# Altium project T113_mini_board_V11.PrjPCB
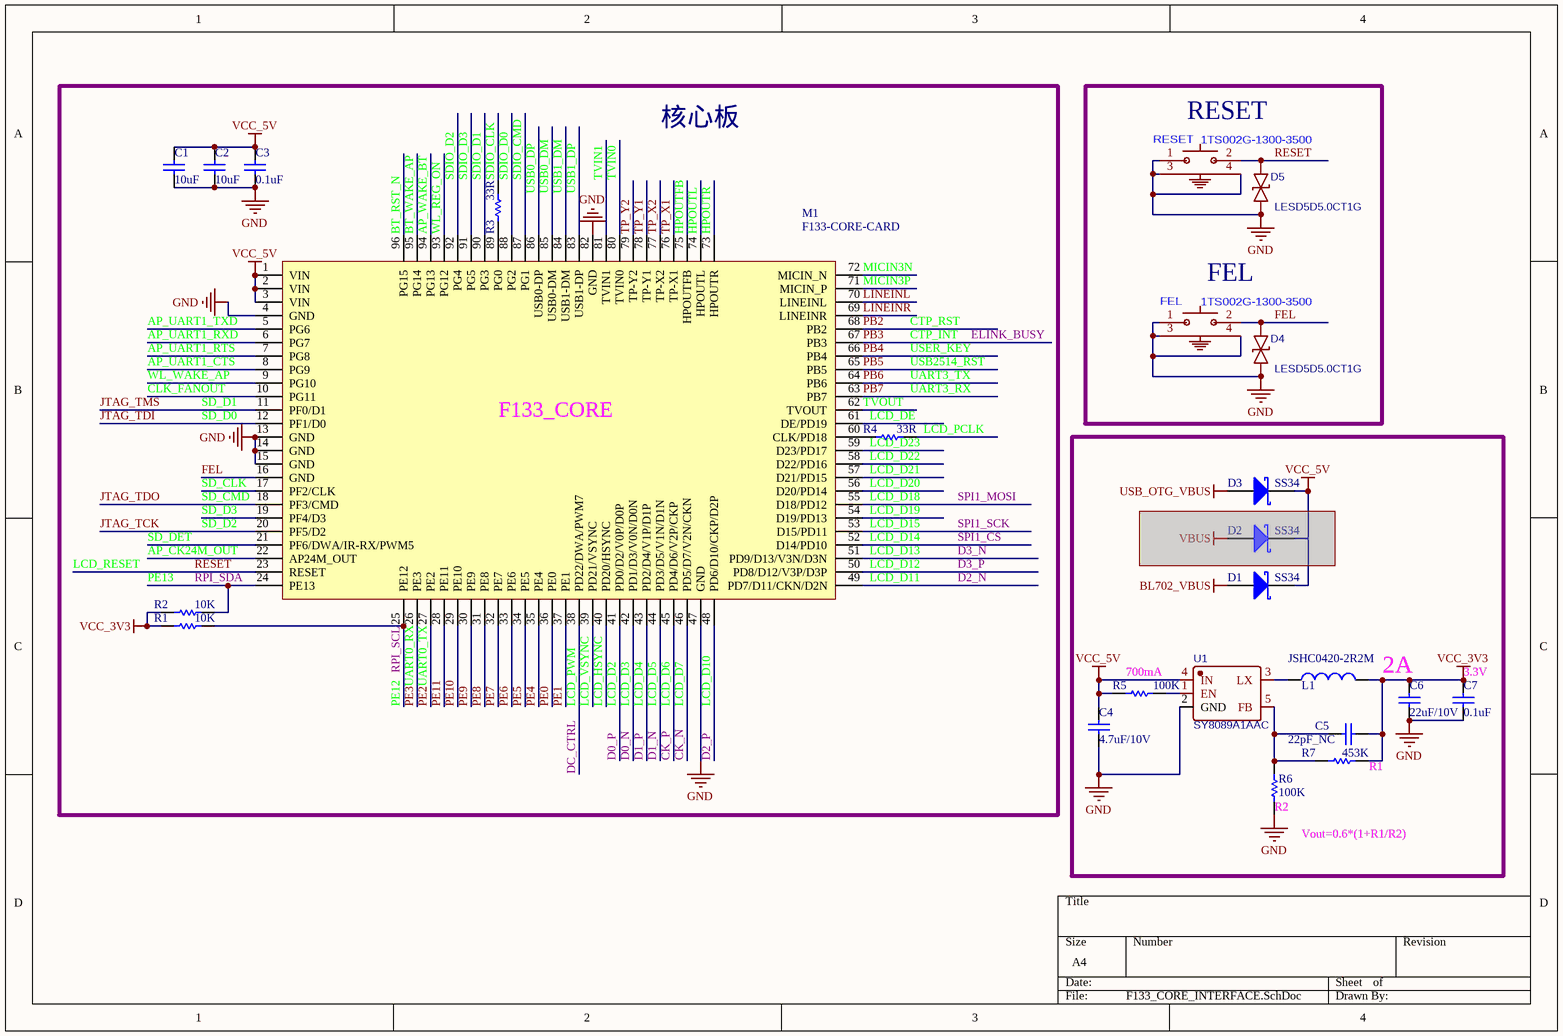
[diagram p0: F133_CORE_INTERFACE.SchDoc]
4 sheets, 114 parts. Net scope: global (net labels, ports and power ports of the same name join across sheets).
Board file: T113_mini_board_V11.PcbDoc
Sheets:
  F133_CORE_INTERFACE.SchDoc
  USB_OTG&DEBUG&TF.SchDoc
  INTERFACE.SchDoc
  BL702.SchDoc

## Sheet F133_CORE_INTERFACE.SchDoc
size A4

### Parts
C1  10uF  [0402]
C2  10uF  [0402]
C3  0.1uF  [0402]
C4  4.7uF/10V  [0402]
C5  22pF_NC  [0402]
C6  22uF/10V  [0603]
C7  0.1uF  [0402]
D1  SS34  [SMA]
D2  SS34  [SMA]  (masked out: inside a compile mask, not in the netlist)
D3  SS34  [SMA]
D4  LESD5D5.0CT1G  [SOD-523_L1.2-W0.8-LS1.6-BI]
D5  LESD5D5.0CT1G  [SOD-523_L1.2-W0.8-LS1.6-BI]
FEL  1TS002G-1300-3500  [SW-SMD_1TS002G-XXXX-3500-CT]
L1  JSHC0420-2R2M  [IND-SMD_L4.9-W4.5]
M1  F133-CORE-CARD  [F133_CORE_V10]
R1  10K  [0402]
R2  10K  [0402]
R3  33R  [0402]
R4  33R  [0402]
R5  100K  [0402]
R6  100K  [0402]
R7  453K  [0402]
RESET  1TS002G-1300-3500  [SW-SMD_1TS002G-XXXX-3500-CT]
U1  SY8089A1AAC  [SOT-23-5_L3.0-W1.7-P0.95-LS2.8-BL]

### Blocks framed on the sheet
核心板: C1-C3 M1 R1-R4
2A: C4-C7 D1-D3 L1 R5-R7 U1

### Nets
BL702_VBUS: D1.1(A)
GND: C1.1 C2.1 C3.1 C4.1 C6.1 C7.1 D4.1 D5.1 FEL.1 FEL.3 FEL.4 M1.4(GND) M1.13(GND) M1.14(GND) M1.15(GND) M1.47(GND) M1.82(GND) R6.2 RESET.1 RESET.3 RESET.4 U1.2(GND)
USB_OTG_VBUS: D3.1(A)
VCC_3V3: C5.2 C6.2 C7.2 L1.2 R1.2 R2.2 R7.1  [project net SYS_3V3]
VCC_5V: C1.2 C2.2 C3.2 C4.2 D1.2(K) D3.2(K) M1.1(VIN) M1.2(VIN) M1.3(VIN) R5.2 U1.4(IN)
AP_CK24M_OUT: M1.22(AP24M_OUT)
AP_UART1_CTS: M1.8(PG9)
AP_UART1_RTS: M1.7(PG8)
AP_UART1_RXD: M1.6(PG7)
AP_UART1_TXD: M1.5(PG6)
AP_WAKE_BT: M1.94(PG13)
BT_RST_N: M1.96(PG15)
BT_WAKE_AP: M1.95(PG14)
CK_N: M1.46(PD5/D7/V2N/CKN)  [also labelled LCD_D7]
CK_P: M1.45(PD4/D6/V2P/CKP)  [also labelled LCD_D6]
CLK_FANOUT: M1.10(PG11)
CTP_INT: M1.67(PB3)  [also labelled ELINK_BUSY, PB3]
CTP_RST: M1.68(PB2)  [also labelled PB2]
D0_N: M1.42(PD1/D3/V0N/D0N)  [also labelled LCD_D3]
D0_P: M1.41(PD0/D2/V0P/D0P)  [also labelled LCD_D2]
D1_N: M1.44(PD3/D5/V1N/D1N)  [also labelled LCD_D5]
D1_P: M1.43(PD2/D4/V1P/D1P)  [also labelled LCD_D4]
D2_N: M1.49(PD7/D11/CKN/D2N)  [also labelled LCD_D11]
D2_P: M1.48(PD6/D10/CKP/D2P)  [also labelled LCD_D10]
D3_N: M1.51(PD9/D13/V3N/D3N)  [also labelled LCD_D13]
D3_P: M1.50(PD8/D12/V3P/D3P)  [also labelled LCD_D12]
DC_CTRL: M1.38(PD22/DWA/PWM7)  [also labelled LCD_PWM]
FEL: D4.2 FEL.2 M1.16(GND)
HPOUTFB: M1.75(HPOUTFB)
HPOUTL: M1.74(HPOUTL)
HPOUTR: M1.73(HPOUTR)
JTAG_TCK: M1.20(PF5/D2)  [also labelled SD_D2]
JTAG_TDI: M1.12(PF1/D0)  [also labelled SD_D0]
JTAG_TDO: M1.18(PF3/CMD)  [also labelled SD_CMD]
JTAG_TMS: M1.11(PF0/D1)  [also labelled SD_D1]
LCD_D14: M1.52(D14/PD10)  [also labelled SPI1_CS]
LCD_D15: M1.53(D15/PD11)  [also labelled SPI1_SCK]
LCD_D18: M1.55(D18/PD12)  [also labelled SPI1_MOSI]
LCD_D19: M1.54(D19/PD13)
LCD_D20: M1.56(D20/PD14)
LCD_D21: M1.57(D21/PD15)
LCD_D22: M1.58(D22/PD16)
LCD_D23: M1.59(D23/PD17)
LCD_DE: M1.61(DE/PD19)
LCD_HSYNC: M1.40(PD20/HSYNC)
LCD_PCLK: R4.2
LCD_RESET: D5.2 M1.23(RESET) RESET.2  [also labelled RESET]
LCD_VSYNC: M1.39(PD21/VSYNC)
LINEINL: M1.70(LINEINL)
LINEINR: M1.69(LINEINR)
MICIN3N: M1.72(MICIN_N)
MICIN3P: M1.71(MICIN_P)
PB4: M1.66(PB4)  [also labelled USER_KEY]
PB5: M1.65(PB5)  [also labelled USB2514_RST]
PB6: M1.64(PB6)  [also labelled UART3_TX]
PB7: M1.63(PB7)  [also labelled UART3_RX]
PE0: M1.36(PE0)
PE1: M1.37(PE1)
PE2: M1.27(PE2)  [also labelled UART0_TX]  [project net BL702_U1RX]
PE3: M1.26(PE3)  [also labelled UART0_RX]  [project net BL702_U1TX]
PE4: M1.35(PE4)
PE5: M1.34(PE5)
PE6: M1.33(PE6)
PE7: M1.32(PE7)
PE8: M1.31(PE8)
PE9: M1.30(PE9)
PE10: M1.29(PE10)
PE11: M1.28(PE11)
PE12: M1.25(PE12) R1.1  [also labelled RPI_SCL]
PE13: M1.24(PE13) R2.1  [also labelled RPI_SDA]
SD_CLK: M1.17(PF2/CLK)
SD_D3: M1.19(PF4/D3)
SD_DET: M1.21(PF6/DWA/IR-RX/PWM5)
SDIO_CLK: R3.1
SDIO_CMD: M1.87(PG1)
SDIO_D0: M1.88(PG2)
SDIO_D1: M1.90(PG3)
SDIO_D2: M1.92(PG4)
SDIO_D3: M1.91(PG5)
TP_X1: M1.76(TP-X1)
TP_X2: M1.77(TP-X2)
TP_Y1: M1.78(TP-Y1)
TP_Y2: M1.79(TP-Y2)
TVIN0: M1.80(TVIN0)
TVIN1: M1.81(TVIN1)
TVOUT: M1.62(TVOUT)
USB0_DM: M1.85(USB0-DM)
USB0_DP: M1.86(USB0-DP)
USB1_DM: M1.84(USB1-DM)
USB1_DP: M1.83(USB1-DP)
WL_REG_ON: M1.93(PG12)
WL_WAKE_AP: M1.9(PG10)
NetC5_1: C5.1 R6.1 R7.2 U1.5(FB)
NetL1_1: L1.1 U1.3(LX)
NetM1_60: M1.60(CLK/PD18) R4.1
NetM1_89: M1.89(PG0) R3.2
NetR5_1: R5.1 U1.1(EN)

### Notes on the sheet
- RESET
- FEL
- (near R5) 700mA
- (near C7) 3.3V
- (near R7) R1
- (near R6) R2
- (near R6) Vout=0.6*(1+R1/R2)

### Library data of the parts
C1-C7 = Cap: Capacitor; PartNumber: CAP100NF
D1-D3 = D Schottky: Schottky Diode
D4 D5 = LESD5D5.0CT1G: BOM_Manufacturer: Leshan Radio; Contributor: LCSC
L1 = Inductor: PartNumber: IND10UH; Code_IEC: 1005
M1 = F133_CORE
R1-R7 = Res1: Resistor; PartNumber: RES2.2K
U1 = SY8089A1AAC: BOM_Manufacturer: Silergy Corp; Contributor: LCSC

## Sheet USB_OTG&DEBUG&TF.SchDoc
size A4
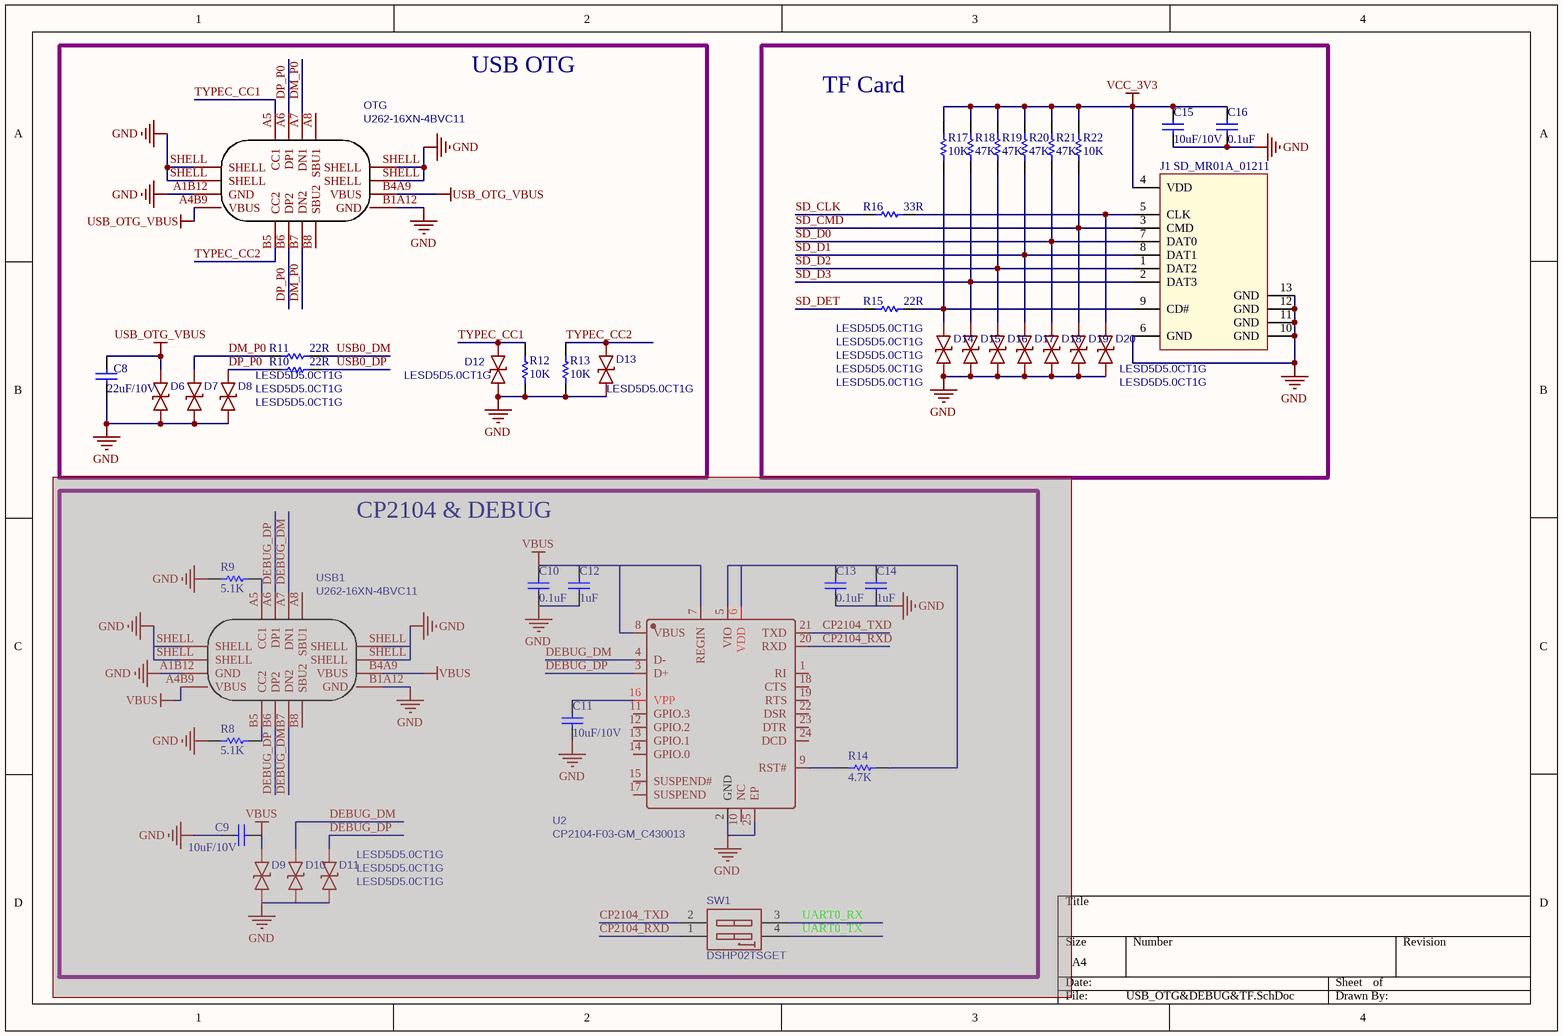
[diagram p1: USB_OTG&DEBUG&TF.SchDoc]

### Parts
C8  22uF/10V  [0603]
C9  10uF/10V  [0402]  (masked out: inside a compile mask, not in the netlist)
C10  0.1uF  [0402]  (masked out: inside a compile mask, not in the netlist)
C11  10uF/10V  [0402]  (masked out: inside a compile mask, not in the netlist)
C12  1uF  [0402]  (masked out: inside a compile mask, not in the netlist)
C13  0.1uF  [0402]  (masked out: inside a compile mask, not in the netlist)
C14  1uF  [0402]  (masked out: inside a compile mask, not in the netlist)
C15  10uF/10V  [0402]
C16  0.1uF  [0402]
D6  LESD5D5.0CT1G  [SOD-523_L1.2-W0.8-LS1.6-BI]
D7  LESD5D5.0CT1G  [SOD-523_L1.2-W0.8-LS1.6-BI]
D8  LESD5D5.0CT1G  [SOD-523_L1.2-W0.8-LS1.6-BI]
D9  LESD5D5.0CT1G  [SOD-523_L1.2-W0.8-LS1.6-BI]  (masked out: inside a compile mask, not in the netlist)
D10  LESD5D5.0CT1G  [SOD-523_L1.2-W0.8-LS1.6-BI]  (masked out: inside a compile mask, not in the netlist)
D11  LESD5D5.0CT1G  [SOD-523_L1.2-W0.8-LS1.6-BI]  (masked out: inside a compile mask, not in the netlist)
D12  LESD5D5.0CT1G  [SOD-523_L1.2-W0.8-LS1.6-BI]
D13  LESD5D5.0CT1G  [SOD-523_L1.2-W0.8-LS1.6-BI]
D14  LESD5D5.0CT1G  [SOD-523_L1.2-W0.8-LS1.6-BI]
D15  LESD5D5.0CT1G  [SOD-523_L1.2-W0.8-LS1.6-BI]
D16  LESD5D5.0CT1G  [SOD-523_L1.2-W0.8-LS1.6-BI]
D17  LESD5D5.0CT1G  [SOD-523_L1.2-W0.8-LS1.6-BI]
D18  LESD5D5.0CT1G  [SOD-523_L1.2-W0.8-LS1.6-BI]
D19  LESD5D5.0CT1G  [SOD-523_L1.2-W0.8-LS1.6-BI]
D20  LESD5D5.0CT1G  [SOD-523_L1.2-W0.8-LS1.6-BI]
J1  SD_MR01A_01211  [SD-MR01A-01211]
OTG  U262-16XN-4BVC11  [TYPEC-12PIN - duplicate]
R8  5.1K  [0402]  (masked out: inside a compile mask, not in the netlist)
R9  5.1K  [0402]  (masked out: inside a compile mask, not in the netlist)
R10  22R  [0402]
R11  22R  [0402]
R12  10K  [0402]
R13  10K  [0402]
R14  4.7K  [0402]  (masked out: inside a compile mask, not in the netlist)
R15  22R  [0402]
R16  33R  [0402]
R17  10K  [0402]
R18  47K  [0402]
R19  47K  [0402]
R20  47K  [0402]
R21  47K  [0402]
R22  10K  [0402]
SW1  DSHP02TSGET  [SW-SMD_4P_DSHP02TSGET]  (masked out: inside a compile mask, not in the netlist)
U2  CP2104-F03-GM_C430013  [QFN-24_L4.0-W4.0-P0.50-TL-EP2.7]  (masked out: inside a compile mask, not in the netlist)
USB1  U262-16XN-4BVC11  [TYPEC-12PIN - duplicate]  (masked out: inside a compile mask, not in the netlist)

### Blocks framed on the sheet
USB OTG: C8 D6-D8 D12 D13 OTG R10-R13
TF Card: C15 C16 D14-D20 J1 R15-R22
CP2104 & DEBUG: C9-C14 D9-D11 R8 R9 R14 SW1 U2 USB1

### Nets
GND: C8.1 C15.2 C16.2 D6.1 D7.1 D8.1 D12.1 D13.1 D14.1 D15.1 D16.1 D17.1 D18.1 D19.1 D20.1 J1.6(GND) J1.10(GND) J1.11(GND) J1.12(GND) J1.13(GND) OTG.A1B12(GND) OTG.B1A12(GND) OTG.SHELL R12.1 R13.1
USB_OTG_VBUS: C8.2 D6.2 OTG.A4B9(VBUS) OTG.B4A9(VBUS)
VCC_3V3: C15.1 C16.1 J1.4(VDD) R17.1 R18.1 R19.1 R20.1 R21.1 R22.1  [project net SYS_3V3]
DM_P0: D7.2 OTG.A7(DN1) OTG.B7(DN2) R11.1
DP_P0: D8.2 OTG.A6(DP1) OTG.B6(DP2) R10.1
SD_CLK: R16.2
SD_CMD: D19.2 J1.3(CMD) R22.2  [project net JTAG_TDO]
SD_D0: D18.2 J1.7(DAT0) R21.2  [project net JTAG_TDI]
SD_D1: D17.2 J1.8(DAT1) R20.2  [project net JTAG_TMS]
SD_D2: D16.2 J1.1(DAT2) R19.2  [project net JTAG_TCK]
SD_D3: D15.2 J1.2(DAT3) R18.2
SD_DET: R15.2
TYPEC_CC1: D12.2 OTG.A5(CC1) R12.2
TYPEC_CC2: D13.2 OTG.B5(CC2) R13.2
USB0_DM: R11.2
USB0_DP: R10.2
NetD14_2: D14.2 J1.9(CD#) R15.1 R17.2
NetD20_2: D20.2 J1.5(CLK) R16.1

Not connected (* = marked no-connect by the designer): OTG A8(SBU1) B8(SBU2)

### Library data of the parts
C8-C16 = Cap: Capacitor; PartNumber: CAP100NF
D6-D13 = LESD5D5.0CT1G: as D4 on sheet F133_CORE_INTERFACE
D14-D20 = LESD5D5.0CT1G: BOM_Manufacturer: Leshan Radio; Contributor: LCSC; BOM_Paste Type: expand
OTG USB1 = U262-16XN-4BVC11: BOM_Manufacturer: XKB Enterprise; Contributor: LCSC
R8 R9 R14-R22 = Res1: Resistor; PartNumber: RES2.2K
R10-R13 = Res1: Resistor; PartNumber: RES22R
SW1 = DSHP02TSGET: BOM_Manufacturer: KE
U2 = CP2104-F03-GM_C430013: BOM_Manufacturer: SILICON LABS; Contributor: LCSC

## Sheet INTERFACE.SchDoc
size A4
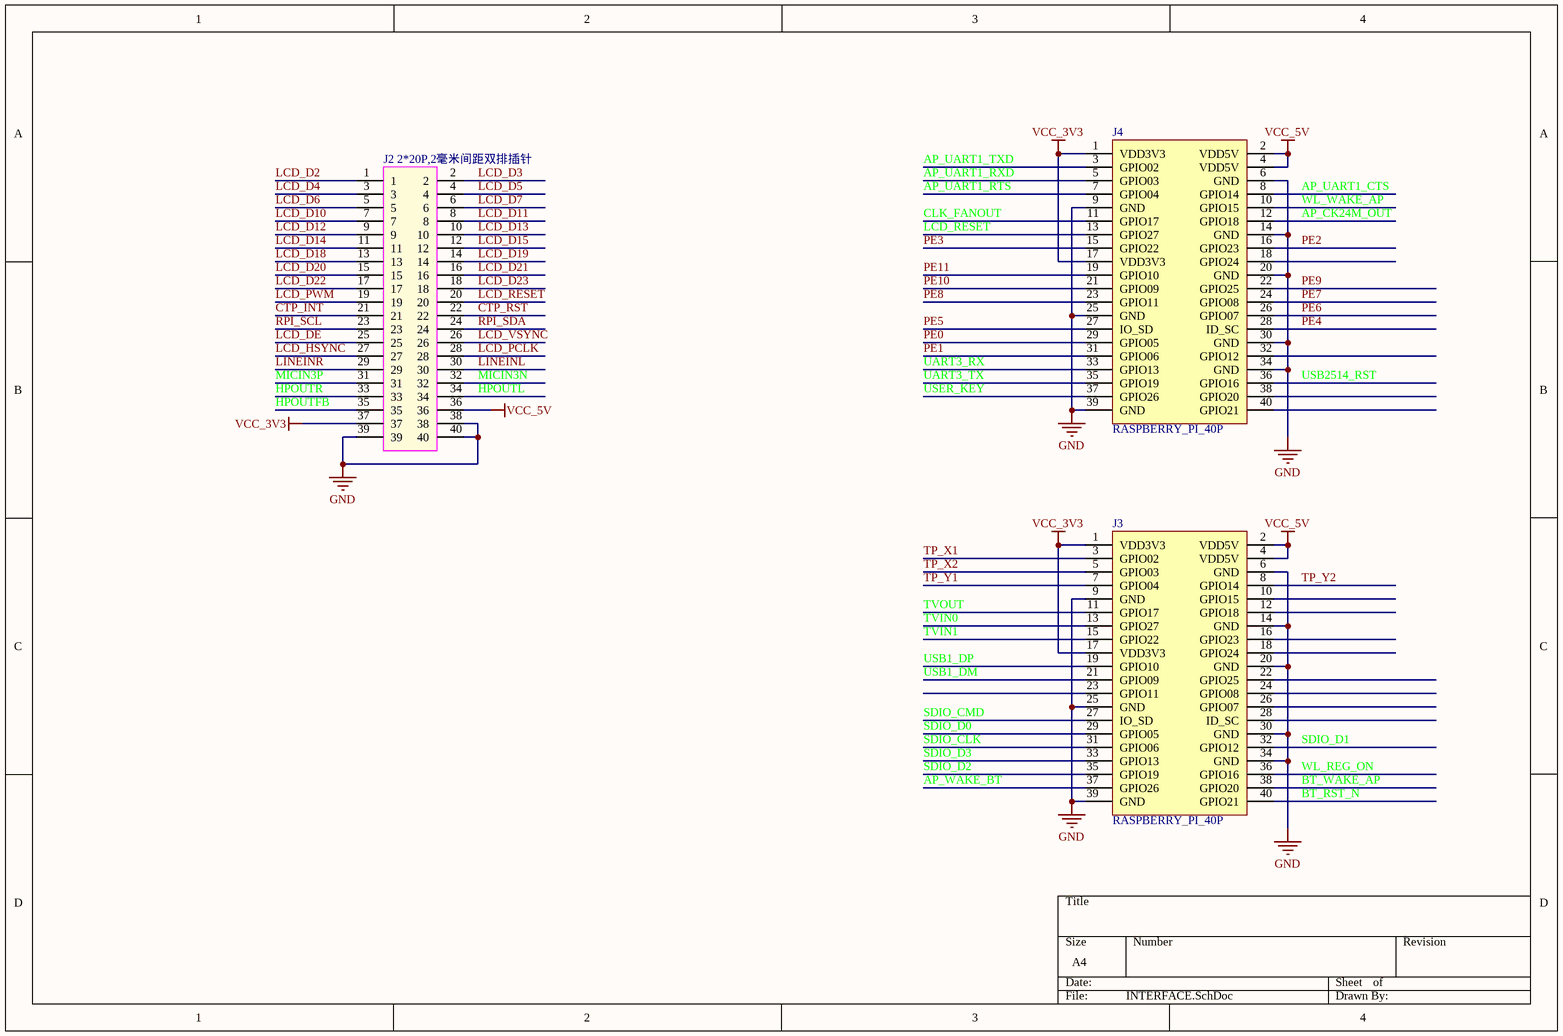
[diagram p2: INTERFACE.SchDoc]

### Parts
J2  2*20P,2毫米间距双排插针  [HDR-TH_40P-P2.00-V-M-R2-C20-S2.00]
J3  RASPBERRY_PI_40P  [IDE2X20]
J4  RASPBERRY_PI_40P  [IDE2X20]

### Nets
GND: J2.38 J2.39 J2.40 J3.6(GND) J3.9(GND) J3.14(GND) J3.20(GND) J3.25(GND) J3.30(GND) J3.34(GND) J3.39(GND) J4.6(GND) J4.9(GND) J4.14(GND) J4.20(GND) J4.25(GND) J4.30(GND) J4.34(GND) J4.39(GND)
VCC_3V3: J2.37 J3.1(VDD3V3) J3.17(VDD3V3) J4.1(VDD3V3) J4.17(VDD3V3)  [project net SYS_3V3]
VCC_5V: J2.36 J3.2(VDD5V) J3.4(VDD5V) J4.2(VDD5V) J4.4(VDD5V)
AP_CK24M_OUT: J4.12(GPIO18)
AP_UART1_CTS: J4.8(GPIO14)
AP_UART1_RTS: J4.7(GPIO04)
AP_UART1_RXD: J4.5(GPIO03)
AP_UART1_TXD: J4.3(GPIO02)
AP_WAKE_BT: J3.37(GPIO26)
BT_RST_N: J3.40(GPIO21)
BT_WAKE_AP: J3.38(GPIO20)
CLK_FANOUT: J4.11(GPIO17)
CTP_INT: J2.21
CTP_RST: J2.22
HPOUTFB: J2.35
HPOUTL: J2.34
HPOUTR: J2.33
LCD_D2: J2.1  [project net D0_P]
LCD_D3: J2.2  [project net D0_N]
LCD_D4: J2.3  [project net D1_P]
LCD_D5: J2.4  [project net D1_N]
LCD_D6: J2.5  [project net CK_P]
LCD_D7: J2.6  [project net CK_N]
LCD_D10: J2.7  [project net D2_P]
LCD_D11: J2.8  [project net D2_N]
LCD_D12: J2.9  [project net D3_P]
LCD_D13: J2.10  [project net D3_N]
LCD_D14: J2.11
LCD_D15: J2.12
LCD_D18: J2.13
LCD_D19: J2.14
LCD_D20: J2.15
LCD_D21: J2.16
LCD_D22: J2.17
LCD_D23: J2.18
LCD_DE: J2.25
LCD_HSYNC: J2.27
LCD_PCLK: J2.28
LCD_PWM: J2.19  [project net DC_CTRL]
LCD_RESET: J2.20 J4.13(GPIO27)
LCD_VSYNC: J2.26
LINEINL: J2.30
LINEINR: J2.29
MICIN3N: J2.32
MICIN3P: J2.31
PE0: J4.29(GPIO05)
PE1: J4.31(GPIO06)
PE2: J4.16(GPIO23)  [project net BL702_U1RX]
PE3: J4.15(GPIO22)  [project net BL702_U1TX]
PE4: J4.28(ID_SC)
PE5: J4.27(IO_SD)
PE6: J4.26(GPIO07)
PE7: J4.24(GPIO08)
PE8: J4.23(GPIO11)
PE9: J4.22(GPIO25)
PE10: J4.21(GPIO09)
PE11: J4.19(GPIO10)
RPI_SCL: J2.23  [project net PE12]
RPI_SDA: J2.24  [project net PE13]
SDIO_CLK: J3.31(GPIO06)
SDIO_CMD: J3.27(IO_SD)
SDIO_D0: J3.29(GPIO05)
SDIO_D1: J3.32(GPIO12)
SDIO_D2: J3.35(GPIO19)
SDIO_D3: J3.33(GPIO13)
TP_X1: J3.3(GPIO02)
TP_X2: J3.5(GPIO03)
TP_Y1: J3.7(GPIO04)
TP_Y2: J3.8(GPIO14)
TVIN0: J3.13(GPIO27)
TVIN1: J3.15(GPIO22)
TVOUT: J3.11(GPIO17)
UART3_RX: J4.33(GPIO13)  [project net PB7]
UART3_TX: J4.35(GPIO19)  [project net PB6]
USB1_DM: J3.21(GPIO09)
USB1_DP: J3.19(GPIO10)
USB2514_RST: J4.36(GPIO16)  [project net PB5]
USER_KEY: J4.37(GPIO26)  [project net PB4]
WL_REG_ON: J3.36(GPIO16)
WL_WAKE_AP: J4.10(GPIO15)

Not connected (* = marked no-connect by the designer): J3 10(GPIO15) 12(GPIO18) 16(GPIO23) 18(GPIO24) 22(GPIO25) 23(GPIO11) 24(GPIO08) 26(GPIO07) 28(ID_SC); J4 18(GPIO24) 32(GPIO12) 38(GPIO20) 40(GPIO21)

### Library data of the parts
J2 = IDC40
J3 J4 = RASPBERRY_PI: Value: 40P树莓派接口插针

## Sheet BL702.SchDoc
size A4
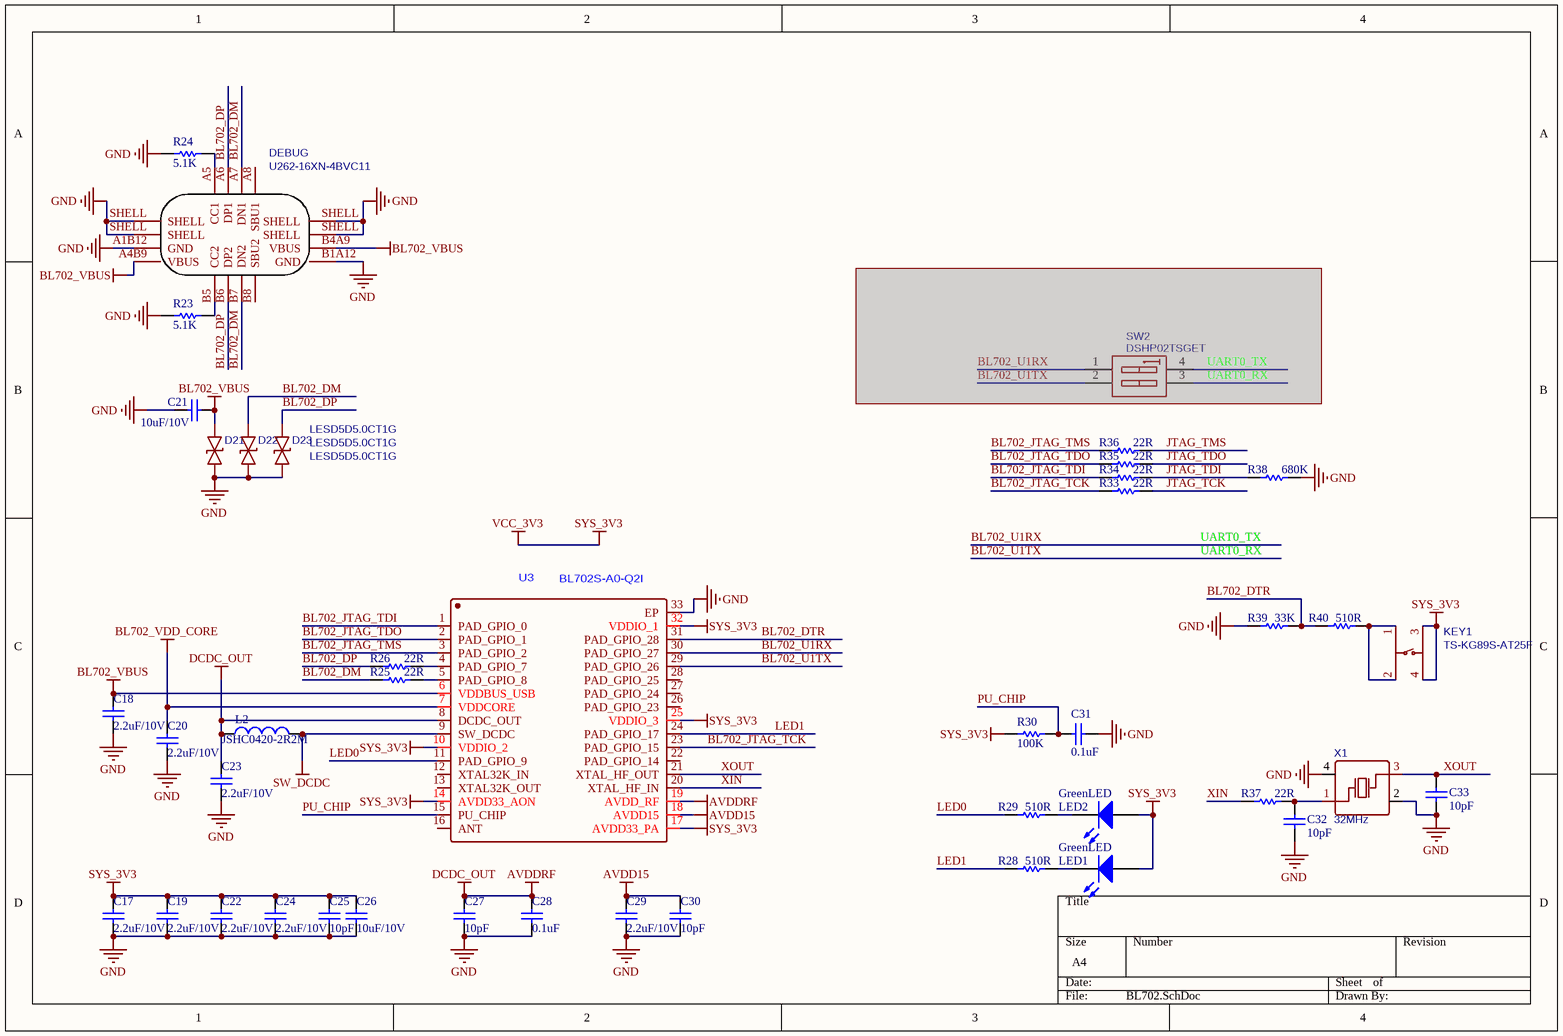
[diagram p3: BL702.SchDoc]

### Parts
C17  2.2uF/10V  [0402]
C18  2.2uF/10V  [0402]
C19  2.2uF/10V  [0402]
C20  2.2uF/10V  [0402]
C21  10uF/10V  [0402]
C22  2.2uF/10V  [0402]
C23  2.2uF/10V  [0402]
C24  2.2uF/10V  [0402]
C25  10pF  [0402]
C26  10uF/10V  [0402]
C27  10pF  [0402]
C28  0.1uF  [0402]
C29  2.2uF/10V  [0402]
C30  10pF  [0402]
C31  0.1uF  [0402]
C32  10pF  [0402]
C33  10pF  [0402]
D21  LESD5D5.0CT1G  [SOD-523_L1.2-W0.8-LS1.6-BI]
D22  LESD5D5.0CT1G  [SOD-523_L1.2-W0.8-LS1.6-BI]
D23  LESD5D5.0CT1G  [SOD-523_L1.2-W0.8-LS1.6-BI]
DEBUG  U262-16XN-4BVC11  [TYPEC-12PIN - duplicate]
KEY1  TS-KG89S-AT25F  [SW-SMD_4P-L4.2-W3.3-P2.15-LS5.1]
L2  JSHC0420-2R2M  [IND-SMD_L4.9-W4.5]
LED1  GreenLED  [LED0402]
LED2  GreenLED  [LED0402]
R23  5.1K  [0402]
R24  5.1K  [0402]
R25  22R  [0402]
R26  22R  [0402]
R28  510R  [0402]
R29  510R  [0402]
R30  100K  [0402]
R33  22R  [0402]
R34  22R  [0402]
R35  22R  [0402]
R36  22R  [0402]
R37  22R  [0402]
R38  680K  [0402]
R39  33K  [0402]
R40  510R  [0402]
SW2  DSHP02TSGET  [SW-SMD_4P_DSHP02TSGET]  (masked out: inside a compile mask, not in the netlist)
U3  BL702S-A0-Q2I  [QFN-32_L4.0-W4.0-P0.40-TL-EP2.9]
X1  32MHz  [OSC-SMD_4P-L3.2-W2.5-BL]

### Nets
AVDD15: C29.2 C30.2 U3.18(AVDD15)
AVDDRF: C23.2 C27.2 C28.2 L2.1 U3.8(DCDC_OUT) U3.19(AVDD_RF)  [also labelled DCDC_OUT]
BL702_VBUS: C18.2 C21.2 D21.2 DEBUG.A4B9(VBUS) DEBUG.B4A9(VBUS) U3.6(VDDBUS_USB)
BL702_VDD_CORE: C20.2 U3.7(VDDCORE)
GND: C17.1 C18.1 C19.1 C20.1 C21.1 C22.1 C23.1 C24.1 C25.1 C26.1 C27.1 C28.1 C29.1 C30.1 C31.1 C32.1 C33.1 D21.1 D22.1 D23.1 DEBUG.A1B12(GND) DEBUG.B1A12(GND) DEBUG.SHELL R23.2 R24.2 R38.1 R39.2 U3.33(EP) X1.2(GND) X1.4(GND)
SW_DCDC: L2.2 U3.9(SW_DCDC)
SYS_3V3: C17.2 C19.2 C22.2 C24.2 C25.2 C26.2 KEY1.3 KEY1.4 LED1.1(A) LED2.1(A) R30.1 U3.10(VDDIO_2) U3.14(AVDD33_AON) U3.17(AVDD33_PA) U3.25(VDDIO_3) U3.32(VDDIO_1)  [also labelled VCC_3V3]
BL702_DM: D22.2 DEBUG.A7(DN1) DEBUG.B7(DN2) R25.2
BL702_DP: D23.2 DEBUG.A6(DP1) DEBUG.B6(DP2) R26.2
BL702_DTR: R39.1 R40.1 U3.31(PAD_GPIO_28)
BL702_JTAG_TCK: R33.2 U3.23(PAD_GPIO_15)
BL702_JTAG_TDI: R34.2 U3.1(PAD_GPIO_0)
BL702_JTAG_TDO: R35.2 U3.2(PAD_GPIO_1)
BL702_JTAG_TMS: R36.2 U3.3(PAD_GPIO_2)
BL702_U1RX: U3.30(PAD_GPIO_27)  [also labelled UART0_TX]
BL702_U1TX: U3.29(PAD_GPIO_26)  [also labelled UART0_RX]
JTAG_TCK: R33.1
JTAG_TDI: R34.1 R38.2
JTAG_TDO: R35.1
JTAG_TMS: R36.1
LED0: R29.1 U3.11(PAD_GPIO_9)
LED1: R28.1 U3.24(PAD_GPIO_17)
PU_CHIP: C31.2 R30.2 U3.15(PU_CHIP)
XIN: R37.2 U3.20(XTAL_HF_IN)
XOUT: C33.2 U3.21(XTAL_HF_OUT) X1.3(OSC2)
NetC32_2: C32.2 R37.1 X1.1(OSC1)
NetDEBUG_A5: DEBUG.A5(CC1) R24.1
NetDEBUG_B5: DEBUG.B5(CC2) R23.1
NetKEY1_1: KEY1.1 KEY1.2 R40.2
NetLED1_2: LED1.2(K) R28.2
NetLED2_2: LED2.2(K) R29.2
NetR25_1: R25.1 U3.5(PAD_GPIO_8)
NetR26_1: R26.1 U3.4(PAD_GPIO_7)

Not connected (* = marked no-connect by the designer): DEBUG A8(SBU1) B8(SBU2); U3 12(XTAL32K_IN) 13(XTAL32K_OUT) 16(ANT) 22(PAD_GPIO_14) 26(PAD_GPIO_23) 27(PAD_GPIO_24) 28(PAD_GPIO_25)

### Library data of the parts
C17-C33 = Cap: Capacitor; PartNumber: CAP100NF
D21-D23 = LESD5D5.0CT1G: as D4 on sheet F133_CORE_INTERFACE
DEBUG = U262-16XN-4BVC11: as OTG on sheet USB_OTG&DEBUG&TF
KEY1 = TS-KG89S-AT25F: Contributor: LCSC
L2 = Inductor: PartNumber: IND10UH; Code_IEC: 1005
LED1 LED2 = LED2: Typical RED, GREEN, YELLOW, AMBER GaAs LED
R23 R24 R28-R30 R40 = Res1: Resistor; PartNumber: RES2.2K
R25 R26 R33-R39 = Res1: Resistor; PartNumber: RES22R
SW2 = DSHP02TSGET: BOM_Manufacturer: KE
X1 = 24MHz_1: BOM_Manufacturer: JGHC; BOM_Manufacturer Part: S3224000151050; nameAlias: Frequency; Contributor: LCSC

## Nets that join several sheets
BL702_VBUS: F133_CORE_INTERFACE (D1.1), BL702 (6 pins)
GND: F133_CORE_INTERFACE (22 pins), USB_OTG&DEBUG&TF (25 pins), INTERFACE (19 pins), BL702 (30 pins)
SYS_3V3: F133_CORE_INTERFACE (7 pins), USB_OTG&DEBUG&TF (9 pins), INTERFACE (5 pins), BL702 (16 pins)
USB_OTG_VBUS: F133_CORE_INTERFACE (D3.1), USB_OTG&DEBUG&TF (C8.2 D6.2 OTG.A4B9 OTG.B4A9)
VCC_5V: F133_CORE_INTERFACE (11 pins), INTERFACE (5 pins)
AP_CK24M_OUT: F133_CORE_INTERFACE (M1.22), INTERFACE (J4.12)
AP_UART1_CTS: F133_CORE_INTERFACE (M1.8), INTERFACE (J4.8)
AP_UART1_RTS: F133_CORE_INTERFACE (M1.7), INTERFACE (J4.7)
AP_UART1_RXD: F133_CORE_INTERFACE (M1.6), INTERFACE (J4.5)
AP_UART1_TXD: F133_CORE_INTERFACE (M1.5), INTERFACE (J4.3)
AP_WAKE_BT: F133_CORE_INTERFACE (M1.94), INTERFACE (J3.37)
BL702_U1RX: F133_CORE_INTERFACE (M1.27), INTERFACE (J4.16), BL702 (U3.30)
BL702_U1TX: F133_CORE_INTERFACE (M1.26), INTERFACE (J4.15), BL702 (U3.29)
BT_RST_N: F133_CORE_INTERFACE (M1.96), INTERFACE (J3.40)
BT_WAKE_AP: F133_CORE_INTERFACE (M1.95), INTERFACE (J3.38)
CK_N: F133_CORE_INTERFACE (M1.46), INTERFACE (J2.6)
CK_P: F133_CORE_INTERFACE (M1.45), INTERFACE (J2.5)
CLK_FANOUT: F133_CORE_INTERFACE (M1.10), INTERFACE (J4.11)
CTP_INT: F133_CORE_INTERFACE (M1.67), INTERFACE (J2.21)
CTP_RST: F133_CORE_INTERFACE (M1.68), INTERFACE (J2.22)
D0_N: F133_CORE_INTERFACE (M1.42), INTERFACE (J2.2)
D0_P: F133_CORE_INTERFACE (M1.41), INTERFACE (J2.1)
D1_N: F133_CORE_INTERFACE (M1.44), INTERFACE (J2.4)
D1_P: F133_CORE_INTERFACE (M1.43), INTERFACE (J2.3)
D2_N: F133_CORE_INTERFACE (M1.49), INTERFACE (J2.8)
D2_P: F133_CORE_INTERFACE (M1.48), INTERFACE (J2.7)
D3_N: F133_CORE_INTERFACE (M1.51), INTERFACE (J2.10)
D3_P: F133_CORE_INTERFACE (M1.50), INTERFACE (J2.9)
DC_CTRL: F133_CORE_INTERFACE (M1.38), INTERFACE (J2.19)
HPOUTFB: F133_CORE_INTERFACE (M1.75), INTERFACE (J2.35)
HPOUTL: F133_CORE_INTERFACE (M1.74), INTERFACE (J2.34)
HPOUTR: F133_CORE_INTERFACE (M1.73), INTERFACE (J2.33)
JTAG_TCK: F133_CORE_INTERFACE (M1.20), USB_OTG&DEBUG&TF (D16.2 J1.1 R19.2), BL702 (R33.1)
JTAG_TDI: F133_CORE_INTERFACE (M1.12), USB_OTG&DEBUG&TF (D18.2 J1.7 R21.2), BL702 (R34.1 R38.2)
JTAG_TDO: F133_CORE_INTERFACE (M1.18), USB_OTG&DEBUG&TF (D19.2 J1.3 R22.2), BL702 (R35.1)
JTAG_TMS: F133_CORE_INTERFACE (M1.11), USB_OTG&DEBUG&TF (D17.2 J1.8 R20.2), BL702 (R36.1)
LCD_D14: F133_CORE_INTERFACE (M1.52), INTERFACE (J2.11)
LCD_D15: F133_CORE_INTERFACE (M1.53), INTERFACE (J2.12)
LCD_D18: F133_CORE_INTERFACE (M1.55), INTERFACE (J2.13)
LCD_D19: F133_CORE_INTERFACE (M1.54), INTERFACE (J2.14)
LCD_D20: F133_CORE_INTERFACE (M1.56), INTERFACE (J2.15)
LCD_D21: F133_CORE_INTERFACE (M1.57), INTERFACE (J2.16)
LCD_D22: F133_CORE_INTERFACE (M1.58), INTERFACE (J2.17)
LCD_D23: F133_CORE_INTERFACE (M1.59), INTERFACE (J2.18)
LCD_DE: F133_CORE_INTERFACE (M1.61), INTERFACE (J2.25)
LCD_HSYNC: F133_CORE_INTERFACE (M1.40), INTERFACE (J2.27)
LCD_PCLK: F133_CORE_INTERFACE (R4.2), INTERFACE (J2.28)
LCD_RESET: F133_CORE_INTERFACE (D5.2 M1.23 RESET.2), INTERFACE (J2.20 J4.13)
LCD_VSYNC: F133_CORE_INTERFACE (M1.39), INTERFACE (J2.26)
LINEINL: F133_CORE_INTERFACE (M1.70), INTERFACE (J2.30)
LINEINR: F133_CORE_INTERFACE (M1.69), INTERFACE (J2.29)
MICIN3N: F133_CORE_INTERFACE (M1.72), INTERFACE (J2.32)
MICIN3P: F133_CORE_INTERFACE (M1.71), INTERFACE (J2.31)
PB4: F133_CORE_INTERFACE (M1.66), INTERFACE (J4.37)
PB5: F133_CORE_INTERFACE (M1.65), INTERFACE (J4.36)
PB6: F133_CORE_INTERFACE (M1.64), INTERFACE (J4.35)
PB7: F133_CORE_INTERFACE (M1.63), INTERFACE (J4.33)
PE0: F133_CORE_INTERFACE (M1.36), INTERFACE (J4.29)
PE1: F133_CORE_INTERFACE (M1.37), INTERFACE (J4.31)
PE4: F133_CORE_INTERFACE (M1.35), INTERFACE (J4.28)
PE5: F133_CORE_INTERFACE (M1.34), INTERFACE (J4.27)
PE6: F133_CORE_INTERFACE (M1.33), INTERFACE (J4.26)
PE7: F133_CORE_INTERFACE (M1.32), INTERFACE (J4.24)
PE8: F133_CORE_INTERFACE (M1.31), INTERFACE (J4.23)
PE9: F133_CORE_INTERFACE (M1.30), INTERFACE (J4.22)
PE10: F133_CORE_INTERFACE (M1.29), INTERFACE (J4.21)
PE11: F133_CORE_INTERFACE (M1.28), INTERFACE (J4.19)
PE12: F133_CORE_INTERFACE (M1.25 R1.1), INTERFACE (J2.23)
PE13: F133_CORE_INTERFACE (M1.24 R2.1), INTERFACE (J2.24)
SD_CLK: F133_CORE_INTERFACE (M1.17), USB_OTG&DEBUG&TF (R16.2)
SD_D3: F133_CORE_INTERFACE (M1.19), USB_OTG&DEBUG&TF (D15.2 J1.2 R18.2)
SD_DET: F133_CORE_INTERFACE (M1.21), USB_OTG&DEBUG&TF (R15.2)
SDIO_CLK: F133_CORE_INTERFACE (R3.1), INTERFACE (J3.31)
SDIO_CMD: F133_CORE_INTERFACE (M1.87), INTERFACE (J3.27)
SDIO_D0: F133_CORE_INTERFACE (M1.88), INTERFACE (J3.29)
SDIO_D1: F133_CORE_INTERFACE (M1.90), INTERFACE (J3.32)
SDIO_D2: F133_CORE_INTERFACE (M1.92), INTERFACE (J3.35)
SDIO_D3: F133_CORE_INTERFACE (M1.91), INTERFACE (J3.33)
TP_X1: F133_CORE_INTERFACE (M1.76), INTERFACE (J3.3)
TP_X2: F133_CORE_INTERFACE (M1.77), INTERFACE (J3.5)
TP_Y1: F133_CORE_INTERFACE (M1.78), INTERFACE (J3.7)
TP_Y2: F133_CORE_INTERFACE (M1.79), INTERFACE (J3.8)
TVIN0: F133_CORE_INTERFACE (M1.80), INTERFACE (J3.13)
TVIN1: F133_CORE_INTERFACE (M1.81), INTERFACE (J3.15)
TVOUT: F133_CORE_INTERFACE (M1.62), INTERFACE (J3.11)
USB0_DM: F133_CORE_INTERFACE (M1.85), USB_OTG&DEBUG&TF (R11.2)
USB0_DP: F133_CORE_INTERFACE (M1.86), USB_OTG&DEBUG&TF (R10.2)
USB1_DM: F133_CORE_INTERFACE (M1.84), INTERFACE (J3.21)
USB1_DP: F133_CORE_INTERFACE (M1.83), INTERFACE (J3.19)
WL_REG_ON: F133_CORE_INTERFACE (M1.93), INTERFACE (J3.36)
WL_WAKE_AP: F133_CORE_INTERFACE (M1.9), INTERFACE (J4.10)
